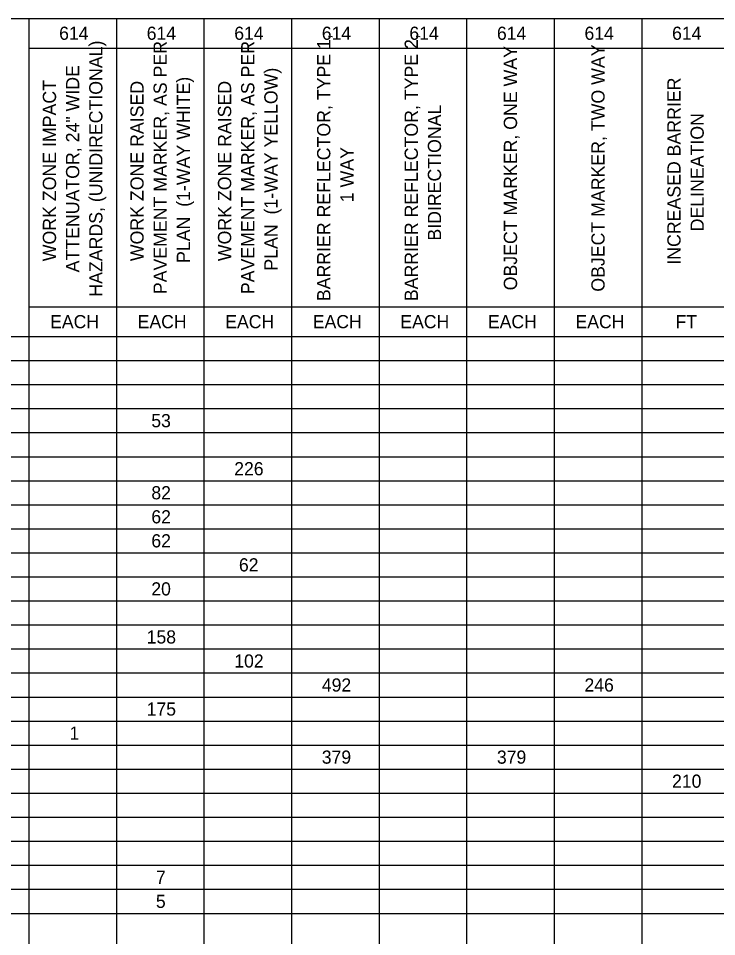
# Model space of a CAD drawing. Extents: x 91011267 to 91022583, y 37007614 to 37014266.
# Drawn here: x 91011644 to 91012044, y 37009420 to 37009945 of the extents above; entities that cross this region are included whole.
import ezdxf

# ---------------------------------------------------------------- set-up
doc = ezdxf.new("R2010")
doc.units = 0
doc.layers.add('SC_Scratch2', color=7, linetype='Continuous')
doc.layers.add('SH_Data', color=7, linetype='Continuous')

msp = doc.modelspace()

# ---------------------------------------------------------------- linework, layer by layer
at = {"layer": 'SC_Scratch2'}
msp.add_lwpolyline([(91011277.35, 37009944.63), (91012802.35, 37009944.63), (91012802.35, 37008894.63), (91011277.35, 37008894.63)], close=True, dxfattribs=at)
at = {"layer": 'SH_Data'}
for p, q in [((91011596.32, 37009944.63), (91011650.36, 37009944.63)), ((91011650.36, 37009944.63), (91011950.88, 37009944.63)), ((91011650.36, 37009944.63), (91011650.36, 37009853.7)), ((91011700.45, 37009944.63), (91011700.45, 37009853.7)), ((91011750.54, 37009944.63), (91011750.54, 37009853.7)), ((91011800.62, 37009944.63), (91011800.62, 37009853.7)), ((91011850.71, 37009944.63), (91011850.71, 37009853.7)), ((91011900.79, 37009944.63), (91011900.79, 37009853.7)), ((91011950.88, 37009944.63), (91012000.97, 37009944.63)), ((91011950.88, 37009944.63), (91011950.88, 37009853.7)), ((91012000.97, 37009944.63), (91012551.92, 37009944.63)), ((91012000.97, 37009944.63), (91012000.97, 37009853.7)), ((91011650.36, 37009927.62), (91011950.88, 37009927.62)), ((91011950.88, 37009927.62), (91012000.97, 37009927.62)), ((91012000.97, 37009927.62), (91012551.92, 37009927.62)), ((91011650.36, 37009853.7), (91011650.36, 37009779.77)), ((91011700.45, 37009853.7), (91011700.45, 37009779.77)), ((91011750.54, 37009853.7), (91011750.54, 37009779.77)), ((91011800.62, 37009853.7), (91011800.62, 37009779.77)), ((91011850.71, 37009853.7), (91011850.71, 37009779.77)), ((91011900.79, 37009853.7), (91011900.79, 37009779.77)), ((91011950.88, 37009853.7), (91011950.88, 37009779.77)), ((91012000.97, 37009853.7), (91012000.97, 37009779.77)), ((91011650.36, 37009779.77), (91011950.88, 37009779.77)), ((91011650.36, 37009779.77), (91011650.36, 37009762.76)), ((91011700.45, 37009779.77), (91011700.45, 37009762.76)), ((91011750.54, 37009779.77), (91011750.54, 37009762.76)), ((91011800.62, 37009779.77), (91011800.62, 37009762.76)), ((91011850.71, 37009779.77), (91011850.71, 37009762.76)), ((91011900.79, 37009779.77), (91011900.79, 37009762.76)), ((91011950.88, 37009779.77), (91012000.97, 37009779.77)), ((91011950.88, 37009779.77), (91011950.88, 37009762.76)), ((91012000.97, 37009779.77), (91012551.92, 37009779.77)), ((91012000.97, 37009779.77), (91012000.97, 37009762.76)), ((91011596.32, 37009762.76), (91011650.36, 37009762.76)), ((91011650.36, 37009762.76), (91011950.88, 37009762.76)), ((91011650.36, 37009762.76), (91011650.36, 37009652.86)), ((91011700.45, 37009762.76), (91011700.45, 37009652.86)), ((91011750.54, 37009762.76), (91011750.54, 37009652.86)), ((91011800.62, 37009762.76), (91011800.62, 37009652.86)), ((91011850.71, 37009762.76), (91011850.71, 37009652.86)), ((91011900.79, 37009762.76), (91011900.79, 37009652.86)), ((91011950.88, 37009762.76), (91012000.97, 37009762.76)), ((91011950.88, 37009762.76), (91011950.88, 37009652.86)), ((91012000.97, 37009762.76), (91012551.92, 37009762.76)), ((91012000.97, 37009762.76), (91012000.97, 37009652.86)), ((91011596.32, 37009749.02), (91011650.36, 37009749.02)), ((91011650.36, 37009749.02), (91011950.88, 37009749.02)), ((91011950.88, 37009749.02), (91012000.97, 37009749.02)), ((91012000.97, 37009749.02), (91012551.92, 37009749.02)), ((91011596.32, 37009735.29), (91011650.36, 37009735.29)), ((91011650.36, 37009735.29), (91011950.88, 37009735.29)), ((91011950.88, 37009735.29), (91012000.97, 37009735.29)), ((91012000.97, 37009735.29), (91012551.92, 37009735.29)), ((91011596.32, 37009721.55), (91011650.36, 37009721.55)), ((91011650.36, 37009721.55), (91011950.88, 37009721.55)), ((91011950.88, 37009721.55), (91012000.97, 37009721.55)), ((91012000.97, 37009721.55), (91012551.92, 37009721.55)), ((91011596.32, 37009707.81), (91011650.36, 37009707.81)), ((91011650.36, 37009707.81), (91011950.88, 37009707.81)), ((91011950.88, 37009707.81), (91012000.97, 37009707.81)), ((91012000.97, 37009707.81), (91012551.92, 37009707.81)), ((91011596.32, 37009694.07), (91011650.36, 37009694.07)), ((91011650.36, 37009694.07), (91011950.88, 37009694.07)), ((91011950.88, 37009694.07), (91012000.97, 37009694.07)), ((91012000.97, 37009694.07), (91012551.92, 37009694.07)), ((91011596.32, 37009680.33), (91011650.36, 37009680.33)), ((91011650.36, 37009680.33), (91011950.88, 37009680.33)), ((91011950.88, 37009680.33), (91012000.97, 37009680.33)), ((91012000.97, 37009680.33), (91012551.92, 37009680.33)), ((91011596.32, 37009666.59), (91011650.36, 37009666.59)), ((91011650.36, 37009666.59), (91011950.88, 37009666.59)), ((91011950.88, 37009666.59), (91012000.97, 37009666.59)), ((91012000.97, 37009666.59), (91012551.92, 37009666.59)), ((91011596.32, 37009652.86), (91011650.36, 37009652.86)), ((91011650.36, 37009652.86), (91011950.88, 37009652.86)), ((91011650.36, 37009652.86), (91011650.36, 37009639.12)), ((91011700.45, 37009652.86), (91011700.45, 37009639.12)), ((91011750.54, 37009652.86), (91011750.54, 37009639.12)), ((91011800.62, 37009652.86), (91011800.62, 37009639.12)), ((91011850.71, 37009652.86), (91011850.71, 37009639.12)), ((91011900.79, 37009652.86), (91011900.79, 37009639.12)), ((91011950.88, 37009652.86), (91012000.97, 37009652.86)), ((91011950.88, 37009652.86), (91011950.88, 37009639.12)), ((91012000.97, 37009652.86), (91012551.92, 37009652.86)), ((91012000.97, 37009652.86), (91012000.97, 37009639.12)), ((91011596.32, 37009639.12), (91011650.36, 37009639.12)), ((91011650.36, 37009639.12), (91011950.88, 37009639.12)), ((91011650.36, 37009639.12), (91011650.36, 37009611.64)), ((91011700.45, 37009639.12), (91011700.45, 37009611.64)), ((91011750.54, 37009639.12), (91011750.54, 37009611.64)), ((91011800.62, 37009639.12), (91011800.62, 37009611.64)), ((91011850.71, 37009639.12), (91011850.71, 37009611.64)), ((91011900.79, 37009639.12), (91011900.79, 37009611.64)), ((91011950.88, 37009639.12), (91012000.97, 37009639.12)), ((91011950.88, 37009639.12), (91011950.88, 37009611.64)), ((91012000.97, 37009639.12), (91012551.92, 37009639.12)), ((91012000.97, 37009639.12), (91012000.97, 37009611.64)), ((91011596.32, 37009625.38), (91011650.36, 37009625.38)), ((91011650.36, 37009625.38), (91011950.88, 37009625.38)), ((91011950.88, 37009625.38), (91012000.97, 37009625.38)), ((91012000.97, 37009625.38), (91012551.92, 37009625.38)), ((91011596.32, 37009611.64), (91011650.36, 37009611.64)), ((91011650.36, 37009611.64), (91011950.88, 37009611.64)), ((91011650.36, 37009611.64), (91011650.36, 37009597.9)), ((91011700.45, 37009611.64), (91011700.45, 37009597.9)), ((91011750.54, 37009611.64), (91011750.54, 37009597.9)), ((91011800.62, 37009611.64), (91011800.62, 37009597.9)), ((91011850.71, 37009611.64), (91011850.71, 37009597.9)), ((91011900.79, 37009611.64), (91011900.79, 37009597.9)), ((91011950.88, 37009611.64), (91012000.97, 37009611.64)), ((91011950.88, 37009611.64), (91011950.88, 37009597.9)), ((91012000.97, 37009611.64), (91012551.92, 37009611.64)), ((91012000.97, 37009611.64), (91012000.97, 37009597.9)), ((91011596.32, 37009597.9), (91011650.36, 37009597.9)), ((91011650.36, 37009597.9), (91011950.88, 37009597.9)), ((91011650.36, 37009597.9), (91011650.36, 37009584.17)), ((91011700.45, 37009597.9), (91011700.45, 37009584.17)), ((91011750.54, 37009597.9), (91011750.54, 37009584.17)), ((91011800.62, 37009597.9), (91011800.62, 37009584.17)), ((91011850.71, 37009597.9), (91011850.71, 37009584.17)), ((91011900.79, 37009597.9), (91011900.79, 37009584.17)), ((91011950.88, 37009597.9), (91012000.97, 37009597.9)), ((91011950.88, 37009597.9), (91011950.88, 37009584.17)), ((91012000.97, 37009597.9), (91012551.92, 37009597.9)), ((91012000.97, 37009597.9), (91012000.97, 37009584.17)), ((91011596.32, 37009584.17), (91011650.36, 37009584.17)), ((91011650.36, 37009584.17), (91011950.88, 37009584.17)), ((91011650.36, 37009584.17), (91011650.36, 37009570.43)), ((91011700.45, 37009584.17), (91011700.45, 37009570.43)), ((91011750.54, 37009584.17), (91011750.54, 37009570.43)), ((91011800.62, 37009584.17), (91011800.62, 37009570.43)), ((91011850.71, 37009584.17), (91011850.71, 37009570.43)), ((91011900.79, 37009584.17), (91011900.79, 37009570.43)), ((91011950.88, 37009584.17), (91012000.97, 37009584.17)), ((91011950.88, 37009584.17), (91011950.88, 37009570.43)), ((91012000.97, 37009584.17), (91012551.92, 37009584.17)), ((91012000.97, 37009584.17), (91012000.97, 37009570.43)), ((91011596.32, 37009570.43), (91011650.36, 37009570.43)), ((91011650.36, 37009570.43), (91011950.88, 37009570.43)), ((91011650.36, 37009570.43), (91011650.36, 37009364.35)), ((91011700.45, 37009570.43), (91011700.45, 37009364.35)), ((91011750.54, 37009570.43), (91011750.54, 37009364.35)), ((91011800.62, 37009570.43), (91011800.62, 37009364.35)), ((91011850.71, 37009570.43), (91011850.71, 37009364.35)), ((91011900.79, 37009570.43), (91011900.79, 37009364.35)), ((91011950.88, 37009570.43), (91012000.97, 37009570.43)), ((91011950.88, 37009570.43), (91011950.88, 37009364.35)), ((91012000.97, 37009570.43), (91012551.92, 37009570.43)), ((91012000.97, 37009570.43), (91012000.97, 37009364.35)), ((91011596.32, 37009556.69), (91011650.36, 37009556.69)), ((91011650.36, 37009556.69), (91011950.88, 37009556.69)), ((91011950.88, 37009556.69), (91012000.97, 37009556.69)), ((91012000.97, 37009556.69), (91012551.92, 37009556.69)), ((91011596.32, 37009542.95), (91011650.36, 37009542.95)), ((91011650.36, 37009542.95), (91011950.88, 37009542.95)), ((91011950.88, 37009542.95), (91012000.97, 37009542.95)), ((91012000.97, 37009542.95), (91012551.92, 37009542.95)), ((91011596.32, 37009529.21), (91011650.36, 37009529.21)), ((91011650.36, 37009529.21), (91011950.88, 37009529.21)), ((91011950.88, 37009529.21), (91012000.97, 37009529.21)), ((91012000.97, 37009529.21), (91012551.92, 37009529.21)), ((91011596.32, 37009515.47), (91011650.36, 37009515.47)), ((91011650.36, 37009515.47), (91011950.88, 37009515.47)), ((91011950.88, 37009515.47), (91012000.97, 37009515.47)), ((91012000.97, 37009515.47), (91012551.92, 37009515.47)), ((91011596.32, 37009501.74), (91011650.36, 37009501.74)), ((91011650.36, 37009501.74), (91011950.88, 37009501.74)), ((91011950.88, 37009501.74), (91012000.97, 37009501.74)), ((91012000.97, 37009501.74), (91012551.92, 37009501.74)), ((91011596.32, 37009488), (91011650.36, 37009488)), ((91011650.36, 37009488), (91011950.88, 37009488)), ((91011950.88, 37009488), (91012000.97, 37009488)), ((91012000.97, 37009488), (91012551.92, 37009488)), ((91011596.32, 37009474.26), (91011650.36, 37009474.26)), ((91011650.36, 37009474.26), (91011950.88, 37009474.26)), ((91011950.88, 37009474.26), (91012000.97, 37009474.26)), ((91012000.97, 37009474.26), (91012551.92, 37009474.26)), ((91011596.32, 37009460.52), (91011650.36, 37009460.52)), ((91011650.36, 37009460.52), (91011950.88, 37009460.52)), ((91011950.88, 37009460.52), (91012000.97, 37009460.52)), ((91012000.97, 37009460.52), (91012551.92, 37009460.52)), ((91011596.32, 37009446.78), (91011650.36, 37009446.78)), ((91011650.36, 37009446.78), (91011950.88, 37009446.78)), ((91011950.88, 37009446.78), (91012000.97, 37009446.78)), ((91012000.97, 37009446.78), (91012551.92, 37009446.78)), ((91011596.32, 37009433.04), (91011650.36, 37009433.04)), ((91011650.36, 37009433.04), (91011950.88, 37009433.04)), ((91011950.88, 37009433.04), (91012000.97, 37009433.04)), ((91012000.97, 37009433.04), (91012551.92, 37009433.04))]:
    msp.add_line(p, q, dxfattribs=at)

# ---------------------------------------------------------------- texts
for s, height, p in [('614', 7.523, (91011667.69, 37009932.37)), ('614', 7.523, (91011717.78, 37009932.37)), ('614', 7.523, (91011767.86, 37009932.37)), ('614', 7.523, (91011817.95, 37009932.37)), ('614', 7.523, (91011868.04, 37009932.37)), ('614', 7.523, (91011918.12, 37009932.37)), ('614', 7.523, (91011968.21, 37009932.37)), ('614', 7.523, (91012018.3, 37009932.37)), ('EACH', 7.523, (91011662.55, 37009767.51)), ('EACH', 7.523, (91011712.64, 37009767.51)), ('EACH', 7.523, (91011762.72, 37009767.51)), ('EACH', 7.523, (91011812.81, 37009767.51)), ('EACH', 7.523, (91011862.89, 37009767.51)), ('EACH', 7.523, (91011912.98, 37009767.51)), ('EACH', 7.523, (91011963.07, 37009767.51)), ('FT', 7.523, (91012020.28, 37009767.51)), ('53', 7.523, (91011720.41, 37009710.92)), ('226', 7.523, (91011767.85, 37009683.44)), ('82', 7.523, (91011720.45, 37009669.7)), ('62', 7.523, (91011720.45, 37009655.96)), ('62', 7.523, (91011720.45, 37009642.23)), ('62', 7.523, (91011770.53, 37009628.49)), ('20', 7.523, (91011720.42, 37009614.75)), ('158', 7.523, (91011717.76, 37009587.27)), ('102', 7.523, (91011767.88, 37009573.53)), ('492', 7.523, (91011817.97, 37009559.8)), ('246', 7.523, (91011968.19, 37009559.8)), ('175', 7.523, (91011717.74, 37009546.06)), ('1', 7.52, (91011673.63, 37009532.32)), ('379', 7.523, (91011817.93, 37009518.58)), ('379', 7.523, (91011918.1, 37009518.58)), ('210', 7.523, (91012018.29, 37009504.84)), ('7', 7.52, (91011723.06, 37009449.89)), ('5', 7.52, (91011723.03, 37009436.15))]:
    msp.add_text(s, height=height, dxfattribs=at).set_placement(p)
for s, height, p in [('HAZARDS, (UNIDIRECTIONAL)', 7.5789, (91011692.46, 37009785.54)), ('PAVEMENT MARKER, AS PER ', 7.5789, (91011729.28, 37009786.99)), ('PAVEMENT MARKER, AS PER ', 7.5789, (91011779.37, 37009786.99)), ('BARRIER REFLECTOR, TYPE 1, ', 7.5789, (91011822.82, 37009782.97)), ('BARRIER REFLECTOR, TYPE 2, ', 7.5789, (91011872.91, 37009782.97)), ('OBJECT MARKER, ONE WAY', 7.5789, (91011929.63, 37009789.16)), ('OBJECT MARKER, TWO WAY', 7.5789, (91011979.71, 37009788.38)), ('ATTENUATOR, 24" WIDE ', 7.5789, (91011679.19, 37009799.44)), ('PLAN  (1-WAY YELLOW)', 7.5789, (91011792.63, 37009800.42)), ('PLAN  (1-WAY WHITE)', 7.5789, (91011742.54, 37009804.81)), ('INCREASED BARRIER ', 7.5789, (91012023.17, 37009803.82)), ('WORK ZONE IMPACT ', 7.5789, (91011665.93, 37009805.79)), ('WORK ZONE RAISED ', 7.5789, (91011716.02, 37009805.85)), ('WORK ZONE RAISED ', 7.5789, (91011766.1, 37009805.85)), ('BIDIRECTIONAL', 7.5789, (91011886.17, 37009817.59)), ('DELINEATION', 7.5789, (91012036.43, 37009822.89)), ('1 WAY', 7.579, (91011836.09, 37009839.54))]:
    msp.add_text(s, height=height, rotation=90, dxfattribs=at).set_placement(p)

doc.saveas('drawing.dxf')
